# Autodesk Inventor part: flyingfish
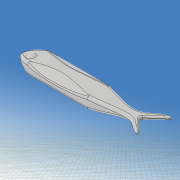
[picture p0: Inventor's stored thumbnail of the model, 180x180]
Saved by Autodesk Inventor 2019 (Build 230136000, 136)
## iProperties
Created: 2020-12
Part Number: flyingfish
Material: 一般
Document SubType Name: Modeling
Designer: kikut
Density: 1 g/cm^3
Appearance: 既定
Mass: 87.6477 g
Surface Area: 156.124 cm^2
Volume: 87.6477 cm^3
Author: kikut
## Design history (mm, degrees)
sketch "スケッチ1"
  geometry: L1 (-100, -20)-(100, -20); L2 (100, -20)-(100, 20); L3 (100, 20)-(-100, 20); L4 (-100, 20)-(-100, -20); L5 (-100, -20)-(100, 20); L6 (100, -20)-(-100, 20); 1 further point
  constraints: 12 end point, 2 midpoint, 2 parallel, 1 horizontal, 1 perpendicular
  dimensions: "d0" = 40 distance of L3.end L1.start; "d1" = 200 distance of L2.end L3.end
extrude "押し出し1" new body sketch "スケッチ1" stored distance "d2" = 60; taper "d3" = 0 deg
sketch "スケッチ2"
  geometry: L1 (0, -60)-(0, 0) reference; L2 (200, -60)-(200, 0) reference; L3 (0, 0)-(200, 0) reference; L4 (200, -60)-(0, -60) reference; L5 (0, -26)-(0, -32); L6 (194, -10)-(194, -13); L7 (194, -13)-(174, -33); L8 (174, -33)-(200, -58); L9 (-20, 20)-(220, 20); L10 (220, 20)-(220, -100); L11 (220, -100)-(-20, -100); L12 (-20, -100)-(-20, 20); 12 further points
  constraints: 16 end point, 4 point on line, 2 parallel, 2 vertical, 1 horizontal, 1 perpendicular, 14 other
  dimensions: "d4" = 32 distance from line of point (32, -12) L1; "d5" = 50 horizontal distance of point (32, -12) point (82, -11); "d6" = 50 horizontal distance of point (132, -17) point (82, -11); "d7" = 12 distance from line of point (32, -12) L3; "d8" = 11 distance from line of point (82, -11) L3; "d10" = 17 distance from line of point (132, -17) L3; "d11" = 26 distance from line of L5.start L3; "d12" = 0 distance from line of point (200, -60) L4; "d13" = 28 distance from line of L5.end L4; "d14" = 12 distance from line of point (28, -48) L4; "d15" = 10 distance from line of point (80, -50) L4; "d16" = 16 distance from line of point (130, -44) L4; "d17" = 28 distance from line of point (28, -48) L1; "d19" = 50 horizontal distance of point (130, -44) point (80, -50); "d20" = 80 distance from line of point (80, -50) L1; "d21" = 6 distance from line of L6.start L2; "d22" = 36 distance from line of point (164, -24) L2; "d23" = 24 distance from line of point (176, -20) L2; "d24" = 10 distance from line of L6.start L3; "d25" = 20 distance from line of point (176, -20) L3; "d26" = 24 distance from line of point (164, -24) L3; "d27" = 40 distance from line of point (160, -40) L2; "d28" = 25 distance from line of point (175, -47.5) L2; "d29" = 12.5 distance from line of point (175, -47.5) L4; "d30" = 20 distance from line of L4 point (160, -40); "d31" = 3 distance of L6.start L6.end; "d32" = 33 distance from line of L7.end L3; "d33" = 26 distance from line of L7.end L2; "d34" = 2 distance of L8.end L2.start; "d35" = 120 distance of L11.end L9.start; "d36" = 240 distance of L10.end L11.end; "d37" = 20 distance between parallel lines of L1 L12; "d38" = 20 distance between parallel lines of L3 L9
extrude "押し出し2" cut sketch "スケッチ2" extent not by distance; stored distance "d39" = 0.02; taper "d40" = 0 deg
sketch "スケッチ8"
  geometry: L1 (-100, -20)-(-100, 20) reference; L2 (100, 20)-(100, -20) reference; L3 (-142.805, 0)-(142.831, 0) reference; L4 (110, 30)-(-110, 30); L5 (-110, 30)-(-110, -30); L6 (-110, -30)-(110, -30); L7 (110, -30)-(110, 30); L8 (110, 30)-(-110, -30); L9 (-110, 30)-(110, -30); L10 (-100, -2)-(-100, 2); L11 (100, -3)-(100, 3); 7 further points
  constraints: 16 end point, 4 point on line, 2 midpoint, 2 parallel, 2 perpendicular, 1 collinear, 1 horizontal, 10 other
  dimensions: "d93" = 2 vertical distance of point (0, 0) L10.end; "d94" = 2 vertical distance of L10.start point (0, 0); "d95" = 35 distance from line of point (-65, -10) L1; "d96" = 0 horizontal distance of point (-65, 10) point (-65, -10); "d97" = 10 vertical distance of point (0, 0) point (-65, -10); "d98" = 10 vertical distance of point (-65, 10) point (0, 0); "d99" = 100 distance from line of point (0, -10) L1; "d100" = 0 horizontal distance of point (0, 10) point (0, -10); "d101" = 10 distance of point (0, -10) point (0, 0); "d102" = 10 distance of point (0, 0) point (0, 10); "d103" = 160 distance from line of point (60, -4) L1; "d104" = 0 horizontal distance of point (60, 4) point (60, -4); "d105" = 4 distance from line of L3 point (60, -4); "d106" = 4 distance from line of L3 point (60, 4); "d107" = 3 distance from line of L11.start L3; "d108" = 3 distance from line of L11.end L3; "d109" = 220 distance of L5.end L6.end; "d110" = 60 distance of L4.end L5.end
extrude "押し出し6" cut sketch "スケッチ8" extent not by distance; stored distance "d111" = 10; taper "d112" = 0 deg
sketch "スケッチ9" dims "d113" = 20, "d114" = 12
  geometry: L1 (-29, -18)-(21, -18); L2 (21, -18)-(21, 22); L3 (21, 22)-(-29, 22); L4 (-29, 22)-(-29, -18); L5 (-29, -18)-(21, 22); L6 (21, -18)-(-29, 22); 2 further points; 1 other entity
  constraints: 12 end point, 2 midpoint, 2 parallel, 1 coincident, 1 horizontal, 1 perpendicular, 2 other
  dimensions: "d115" = 50 distance of L2.end L3.end; "d116" = 40 distance of L1.end L2.end
extrude "押し出し7" cut sketch "スケッチ9" distance "d117" = 150; taper "d118" = 0 deg
fillet "フィレット4" dims "d119" = 4
fillet "フィレット5" dims "d120" = 4
fillet "フィレット6" dims "d121" = 2
node "作業平面2"
sketch "スケッチ10"
  geometry: L1 (0, -41.439)-(0, 38.458) reference; L2 (141.833, 0)-(-140.631, 0) reference; L3 (82.55, 12.983)-(81.45, -4.983); A1 r 9 centre (82, 4) between (82.55, 12.983) and (81.45, -4.983); 1 further point
  constraints: 2 end point, 2 point on circle, 1 centre point
  dimensions: "d123" = 82 distance from line of L1 A1.centre; "d124" = 4 distance from line of L2 A1.centre; "d125" = 9 radius of A1; "d126" = 180 deg dimension on A1.centre L3.end L3.start; "d127" = 90 deg dimension on L3.end point (0, 0) A1.centre
revolve "回転1" sketch "スケッチ10" stored, may be unused: angle "d128" = 90 deg
mirror "ミラー1"
node "ソリッド1"
other parameters: "d122" = -1
